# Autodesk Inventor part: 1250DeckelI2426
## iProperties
Category: PARTsolutions
Created: 2011-08
Part Number: 1250DeckelI2426
Catalog Web Link: www.cadenas.de
Description: 1250 Deckel Innen - Deckel Innen
Document SubType Name: Modeling
Designer: PARTsolutions
Density: 1 g/cm^3
Mass: 138.615 g
Surface Area: 989.189 cm^2
Volume: 138.615 cm^3
NB: 1250DeckelI2426
NN: 1250 Deckel Innen
NT: Deckel Innen
NBSYN: 1250DeckelI2426
LINA: 1250DeckelI2426
BEST: 1250DeckelI
BI: 242
BIMIN: 101.000
BIMAX: 751.000
BKMIN: 150.000
BKMAX: 800.000
STEGV: 6
BST: 267.000
KT: DUMMY
SUPPLIER: Kabelschlepp
ARTICLENO: 1250DeckelI2426
BOMINFO: 1250DeckelI2426
CREATOR: CADENAS GmbH
PSOL_IDENT_0: {\\10.0.0.251\ps_data\23d-libs\kabelschlepp\4_eketten_st\parts\1250_deckel_i.prj},191 {VTYP=3D},{NB=
PSOL_IDENT_1: 1250DeckelI2426},{LINA=1250DeckelI2426},{NN=1250 Deckel Innen},{DATE=21.04.2010 06:13:26},{GEOMDATE=
PSOL_IDENT_2: 21.04.2010 06:13:00},{VERSION=},{LINEID=10},{LINESUBID=-1},{WBVAR=BI,STEGV}  {NB=1250DeckelI2426},{L
PSOL_IDENT_3: INA=1250DeckelI2426},{KT=DUMMY},{BEST=1250DeckelI},{BI=242},{BIMIN=101},{BIMAX=751},{BKMIN=150},{BKM
PSOL_IDENT_4: AX=800},{STEGV=6},{BST=267}
Title: 1250DeckelI2426
Author: Cadenas PARTsolutions
Comments: Deckel Innen
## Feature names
1. Extrusion1
2. Extrusion2
3. Extrusion3
4. Extrusion4
